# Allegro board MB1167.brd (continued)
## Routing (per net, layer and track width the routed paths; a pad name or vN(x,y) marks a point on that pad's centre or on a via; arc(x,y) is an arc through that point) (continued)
NETR47_1: length 2.4
  TOP w0.127: U6.44 127.27,128.51 R47.1
NETR47_2: length 127.9
  TOP w0.127: v1(125.09,158.62) 125.09,158.37 125.83,157.63 125.83,144.12 125.35,143.64 125.35,137.06 125.83,136.58 125.83,131.47 R47.2
  L4_SIG w0.102: v1(102.36,157.61) 102.87,157.61 103.89,158.62 v1(125.09,158.62)
  BOTTOM w0.127: SB55.2 50.7,131.09 50.7,137.78 55.51,142.59 55.51,147.84 61.49,153.83 64.8,153.83 68.2,157.23 69.47,157.23 69.98,157.73 80.34,157.73 80.92,158.32 93.42,158.32 93.83,158.72 101.24,158.72 v1(102.36,157.61)
NETR48_1: length 2.7
  TOP w0.127: U6.43 127.76,126.15 127.76,127.13 128.52,127.89 R48.1
NETR48_2: length 152.3
  TOP w0.127: v1(126.85,152.91) 126.36,152.43 126.36,132.21 R48.2
  BOTTOM w0.127: v1(126.85,152.91) 126.85,153.92 116.84,163.93 116.84,167.26 114.3,169.8 44.83,169.8 42.04,167 42.04,161.57 36.83,156.37 36.83,141.22 39.5,138.56 40.64,138.56
NETR49_1: length 2.6
  TOP w0.127: U6.39 129.77,127.1 130.18,127.51 R49.1
NETR49_2: length 113.6
  TOP w0.127: v1(128.14,132.97) 128.14,132.84 130.18,130.81 R49.2
  BOTTOM w0.127: SB37.1 48.26,143 51.49,146.23 51.49,149.53 60.71,158.75 62.99,158.75 66.29,162.05 82.55,162.05 83.82,160.78 91.59,160.78 92.46,161.65 111.02,161.65 118.67,154 118.67,152.48 127.51,143.64 127.51,133.6 v1(128.14,132.97)
NETR50_1: length 2.9
  TOP w0.127: U6.38 130.27,127.09 131.44,128.27 R50.1
NETR50_2: length 112.3
  TOP w0.127: R50.2 131.44,130.81 v1(128.14,134.11)
  BOTTOM w0.127: SB29.1 48.9,150.5 48.9,152.78 58.29,162.18 61.34,162.18 61.85,162.69 64.01,162.69 65.15,163.83 109.86,163.83 119.63,154.05 119.63,152.65 128.14,144.15 v1(128.14,134.11)
NETR51_1: length 16.8
  TOP w0.127: U4.P8 73.23,137.67 70.51,137.67 64.52,131.67 R51.1
NETR52_1: length 15.4
  TOP w0.127: R52.1 65.53,131.59 70.85,136.91 71.79,136.91 71.8,136.92 73.18,136.92 U4.P9
NETR53_1: length 14.8
  TOP w0.127: U4.N9 74.01,136.09 71.11,136.09 66.55,131.53 R53.1
NETR54_1: length 12.6
  TOP w0.127: U4.P10 73.21,135.29 71.38,135.29 67.56,131.47 R54.1
NETR55_1: length 10.9
  TOP w0.127: R55.1 68.58,130.86 71.45,133.73 71.88,133.73 72.64,134.49 73.22,134.49 U4.P11
NETR56_2: length 7
  TOP w0.127: R56.2 70.99,128.12 72.64,129.77 72.64,130.94 73.21,131.5 73.21,132.09 U4.P14
NETR57_2: length 6.7
  TOP w0.127: U4.N14 74.02,132.09 74.02,131.29 73.41,130.68 73.41,129.22 72.39,128.21 R57.2
NETR58_2: length 5.7
  TOP w0.127: U4.M15 75.21,131.6 75.06,131.44 75.06,130.84 74.93,130.71 74.93,130.3 74.17,129.54 74.17,128.91 73.79,128.52 R58.2
NETR59_1: length 5.4
  TOP w0.127: U4.L15 76.01,131.13 75.69,130.81 75.69,129.92 75.18,129.41 R59.1
NETR60_1: length 7.2
  TOP w0.127: U4.K13 v5(76.41,132.89) ; R60.1 v3(76.45,127.38)
  BOTTOM w0.127: v3(76.45,127.38) 75.95,127.89 75.95,131.32 76.41,131.78 v5(76.41,132.89)
NETR61_1: length 6.7
  TOP w0.127: R61.1 79.3,126.95 79.3,127.54 78.74,128.1 78.74,128.48 77.98,129.24 77.98,132.06 U4.H14
NETR62_1: length 2.2
  TOP w0.127: U6.1 121.62,124.54 R62.1
NETR62_2: length 113.8
  TOP w0.127: R62.2 121.54,135.2 v1(120.47,136.27)
  BOTTOM w0.127: SB41.2 47.77,139.32 53.01,144.56 53.01,148.77 60.83,156.59 63.3,156.59 66.34,159.64 67.97,159.64 68,159.66 68.08,159.66 68.49,160.07 76.63,160.07 77.34,160.78 81.08,160.78 81.76,160.1 91.85,160.1 92.61,160.86 105.71,160.86 110.62,155.96 110.62,142.09 112.88,139.83 116.84,139.83 120.4,136.27 v1(120.47,136.27)
NETR63_1: length 18.6
  TOP w0.127: U4.R8 70.69,137.29 65.02,131.62 65.02,123.83 R63.1
NETR64_1: length 17.3
  TOP w0.127: U4.R9 72.48,136.49 72.44,136.53 71,136.53 66.04,131.56 66.04,123.83 R64.1
NETR65_1: length 15.9
  TOP w0.127: R65.1 67.06,123.83 67.06,131.5 71.24,135.69 U4.R10
NETR66_1: length 14.2
  TOP w0.127: R66.1 68.07,123.83 68.07,130.94 71.37,134.24 72.01,134.24 72.66,134.89 U4.R11
NETR67_1: length 12.8
  TOP w0.127: U4.R12 72.07,133.35 71.68,133.35 69.01,130.68 69.01,129.03 69.09,128.96 69.09,123.83 R67.1
NETR68_2: length 9.5
  TOP w0.127: U4.P15 73.61,131.39 73.03,130.81 73.03,129.49 71.5,127.97 71.5,124.59 70.99,124.08 R68.2
NETR69_2: length 9.2
  TOP w0.127: R69.2 72.39,123.83 72.9,124.33 72.9,128.18 73.79,129.07 73.79,130.57 74.41,131.19 U4.N15
NETR70_1: length 10.1
  TOP w0.127: R70.1 73.79,123.95 74.3,124.46 74.3,128.49 74.55,128.75 74.55,129.38 75.31,130.14 75.31,131.06 75.62,131.37 75.62,132.09 U4.L14
NETR71_1: length 9.1
  TOP w0.127: R71.1 75.82,123.95 75.82,129.29 76.82,130.29 76.82,131.67 U4.K15
NETR72_1: length 12.1
  TOP w0.127: U4.L12 v5(75.61,133.69) ; R72.1 v3(76.45,124.08)
  BOTTOM w0.127: v3(76.45,124.08) 76.96,124.59 76.96,125.09 76.07,125.98 76.07,127 75.56,127.51 75.56,131.46 76.04,131.94 76.04,133.26 v5(75.61,133.69)
NETR73_1: length 3
  TOP w0.254: R73.1 135,123.06 132.39,123.06 U6.33
NETR74_2: length 124.8
  TOP w0.127: v1(122.28,120.8) R74.2 121.54,121.54 U6.7 ; v1(56.73,41.4) U22.26
  L4_SIG w0.102: v1(116,90.37) 114.02,88.39 114.02,80.01 77.83,43.81 75.62,43.81 73.84,42.04 57.62,42.04 56.99,41.4 v1(56.73,41.4)
  BOTTOM w0.127: v1(116,90.37) 116.23,90.6 116.23,112.14 123.04,118.95 123.04,120.29 122.53,120.8 v1(122.28,120.8)
NETR77_1: length 4.4
  TOP w0.127: R77.1 134.24,118.24 134.24,118.77 132.97,120.04 U6.27
NETR80_2: length 4.7
  TOP w0.254: R80.2 R84.1 v1(12.95,111.25)
  BOTTOM w0.254: T6.1 12.51,111.69 v1(12.95,111.25)
NETR81_1: length 2.6
  TOP w0.127: U6.20 128.77,116.07 R81.1
NETR82_1: length 2.3
  TOP w0.127: U6.21 129.27,115.21 R82.1
NETR83_2: length 3.4
  TOP w0.127: R83.2 132.08,117.19 131.83,117.44 U6.24
NETR88_1: length 5.1
  TOP w0.127: R88.1 33.27,109.98 32.26,109.98 31.62,109.35 31.62,108.2 31.21,107.8 U8.24
NETR90_1: length 7.2
  TOP w0.102: 76.45,107.95 76.45,105.83 U9.F2
  TOP w0.127: 76.45,107.95 76.45,109.98 R91.1 R90.1
NETR94_2: length 5.8
  TOP w0.508: U7.4 19.87,112.59 20.57,111.89 SB15.2 R94.2 SB14.2
NETR95_1: length 3.9
  TOP w0.127: R95.1 31.73,107.29 U8.23
NETR98_2: length 2.6
  TOP w0.127: R98.2 26.58,108.58 U8.32
NETR100_1: length 3.7
  TOP w0.127: U8.22 32.75,106.8 R100.1
NETR102_1: length 3.4
  TOP w0.127: U8.21 33.52,106.29 R102.1
NETR103_1: length 2
  TOP w0.254: R103.1 24.39,106.29 U8.4
NETR105_2: length 5.5
  TOP w0.254: R108.2 R105.2 v1(12.95,106.68)
  BOTTOM w0.254: T7.1 11.75,105.48 v1(12.95,106.68)
NETR106_1: length 3.3
  TOP w0.127: U8.20 33.78,105.8 R106.1
NETR107_1: length 61.7
  TOP w0.102: v5(63.79,76.73) U14.G5 ; v4(82.68,102.37) U9.A5
  TOP w0.127: v1(86.87,103.38) R107.1
  L4_SIG w0.102: v1(86.87,103.38) 86.48,102.99 83.31,102.99 82.68,102.37 v4(82.68,102.37)
  BOTTOM w0.127: v4(82.68,102.37) 82.34,102.37 80,104.7 80,105.66 80.48,106.14 80.48,107.63 79.15,108.97 73.38,108.97 65.02,100.61 65.02,90.65 64.89,90.53 63.37,90.53 63.25,90.4 63.25,80.37 63.12,80.24 61.87,80.24 61.75,80.11 61.75,77.83 62.47,77.1 63.42,77.1 v5(63.79,76.73)
NETR109_1: length 3.6
  TOP w0.127: R109.1 32.88,105.29 U8.19
NETR110_2: length 10
  TOP w0.127: T1.3 18.29,102.7 18.8,103.21 18.8,103.63 R110.2 21.46,104.01 22.35,103.12 25.03,103.12 25.53,103.62 U8.9
NETR115_1: length 4.2
  TOP w0.127: U8.18 31.34,104.8 31.58,105.03 31.88,105.03 R115.1
NETR119_1: length 4.6
  TOP w0.127: U8.17 31.21,104.29 32.89,102.62 32.89,102.11 33.53,101.47 R119.1
NETR121_1: length 99.3
  TOP w0.127: R121.1 22.86,98.55 25.3,96.11 v1(26.57,96.11) ; v1(55.5,33.34) 55.49,33.34 55.23,33.59 U22.29
  L4_SIG w0.102: v1(55.5,33.34) 52.45,33.34 52.13,33.02 51.05,33.02 48.46,30.43 41.68,30.43 37.85,34.26 34.7,34.26 32.05,36.91 32.05,61.93 28.8,65.18 28.8,93.5 26.57,95.73 v1(26.57,96.11)
NETR123_1: length 3.8
  TOP w0.127: R123.1 26.42,101.85 27.05,101.85 27.7,102.5 U8.11
NETR124_1: length 3
  TOP w0.127: R124.1 28.2,102.11 U8.12
NETR125_1: length 2.5
  TOP w0.127: R125.1 28.7,101.1 U8.13
NETR126_1: length 2.9
  TOP w0.127: U8.14 29.2,101.99 29.97,101.22 R126.1
NETR127_1: length 5.5
  TOP w0.127: R127.1 19.94,97.92 18.29,97.92 R128.2 17.34,98.87 T1.1
NETR129_2: length 6.2
  TOP w0.508: R129.2 12.29,97.28 ; R129.2 11.68,96.68 ; R129.2 11.07,97.28 ; 12.6,97.28 R130.1 ; R130.1 13.82,97.28 ; R130.1 13.21,96.68 ; U11.4 11.62,96.46 ; U11.4 12.14,95.69 ; U11.4 11.1,95.69 ; U11.4 11.62,94.91
NETR130_2: length 106.7
  TOP w0.127: U22.17 57.42,32.9 v1(56.9,32.38) ; R130.2 v1(14.99,98.81)
  L4_SIG w0.102: v1(14.99,98.81) 22.73,98.81 28.52,93.01 28.52,65.06 31.72,61.86 31.72,36.84 34.53,34.04 37.69,34.04 41.63,30.1 52.3,30.1 55.11,32.9 56.38,32.9 v1(56.9,32.38)
NETR132_1: length 100.6
  TOP w0.127: v1(57.52,32.23) 57.53,32.23 57.71,32.41 U22.16 ; R132.1 14.15,91.44 18.29,87.3 v1(28.09,87.3)
  L4_SIG w0.102: v1(28.09,87.3) 28.22,87.17 28.22,64.95 31.39,61.77 31.39,36.81 34.45,33.76 37.57,33.76 41.5,29.82 52.63,29.82 55.32,32.51 56.01,32.51 56.64,31.88 57.17,31.88 v1(57.52,32.23)
NETR138_2: length 6.7
  TOP w0.127: R138.2 R139.2 11.43,81.66 10.67,82.42 10.67,83.84 T2.1
NETR146_1: length 7.8
  TOP w0.102: 68.71,73.66 68.71,75.69 68.29,76.11 68.29,76.73 U14.B5
  TOP w0.127: R147.1 R146.1 68.71,71.37 68.71,73.66
NETR150_2: length 1.6
  TOP w0.254: R150.2 38.89,59.05 R151.1
NETR151_2: length 4.3
  TOP w0.254: R152.2 39.4,58.04 37.49,58.04 U17.5
NETR152_1: length 1.3
  TOP w0.254: R153.2 R152.1
NETR154_1: length 131.9
  TOP w0.127: v1(133.4,54.76) 138.15,54.76 138.94,53.98 R155.1 139.83,53.85 141.86,55.88 R154.1 ; v1(55.78,36.83) 55.73,36.88 U22.28
  BOTTOM w0.127: v1(55.78,36.83) 56.29,36.32 56.29,35.66 59.31,32.64 59.31,30.99 63.75,26.54 63.75,24.13 67.44,20.45 125.27,20.45 133.4,28.57 v1(133.4,54.76)
NETR167_1: length 1.9
  TOP w0.127: U22.21 60.22,34.9 R167.1
NETR167_2: length 2
  TOP w0.127: U22.22 59.92,35.41 R167.2
NETR171_2: length 2.2
  TOP w0.127: T3.2 18.1,32.96 17.65,32.51 R171.2
NETR172_1: length 2.2
  TOP w0.127: R172.1 49.16,32.9 U22.44
NETR173_2: length 2.6
  TOP w0.127: U21.44 30.35,32.9 29.21,31.76 R173.2
NETR175_1: length 4.1
  TOP w0.127: R176.1 48.26,29.84 R175.1 48.9,31.62 48.9,32.13 49.17,32.41 U22.45
NETR180_1: length 5.1
  TOP w0.127: U22.2 52.23,28.61 R181.2 49.78,27.05 R180.1
NETR184_2: length 3.5
  TOP w0.127: U21.2 33.44,28.61 33.02,28.19 32.27,28.19 31.25,27.18 R184.2
NETR185_2: length 2.7
  TOP w0.127: U21.3 33.94,28.6 R185.2
NETR188_1: length 12.1
  TOP w0.089: U23.D4 117.86,28.58 118.11,28.83 v2(118.11,28.83) U23.D5
  TOP w0.127: v1(124.26,25.02) 124.26,25.22 R188.1
  L4_SIG w0.102: v2(118.11,28.83) 118.11,28.33 118.72,27.72 118.72,25.4 120.09,24.03 121.97,24.03 122.96,25.02 v1(124.26,25.02)
NETR189_2: length 13.2
  TOP w0.089: U23.F3 v2(119.11,28.33)
  TOP w0.127: v1(126.52,24.92) 126.52,25.68 R189.2
  L4_SIG w0.089: v2(119.11,28.33) 119.11,26.67
  L4_SIG w0.102: v1(126.52,24.92) 125.32,26.11 123.27,26.11 121.56,24.41 120.47,24.41 119.11,25.77 119.11,26.67
NETR193_1: length 4.6
  TOP w0.089: U23.E3 118.61,27.83 118.61,26.69 118.63,26.67
  TOP w0.127: 118.63,26.67 118.63,26.28 119.63,25.27 R193.1
NETR194_2: length 4.9
  TOP w0.089: 119.89,26.67 119.61,26.94 119.61,27.33 U23.G2
  TOP w0.127: R194.2 119.89,26.54 119.89,26.67
NETR195_2: length 5.6
  TOP w0.127: U23.H1 120.76,26.19 121.64,26.19 122.56,25.27 123.24,25.27 123.83,24.69 R195.2
NETR199_1: length 3.4
  TOP w0.127: U24.2 123.78,15.66 123.19,16.26 122.68,16.26 122.43,16 122.43,15.49 R199.1
NETR204_1: length 64.2
  TOP w0.127: v1(57.66,30.73) 57.83,30.9 U22.13 ; R204.1 v1(21.21,15.49)
  BOTTOM w0.127: v1(21.21,15.49) 22.61,14.1 26.29,14.1 30.1,10.29 58.42,10.29 60.71,12.57 60.71,21.72 58.93,23.5 58.93,29.46 v1(57.66,30.73)
NETR205_1: length 58.5
  TOP w0.127: R205.1 v1(23.24,15.49) ; U22.12 57.23,28.68 v1(57.66,28.25)
  BOTTOM w0.127: v1(57.66,28.25) 57.66,28.19 58.55,27.3 58.55,23.11 60.2,21.46 60.2,12.7 58.17,10.67 30.48,10.67 26.29,14.86 23.88,14.86 v1(23.24,15.49)
NETR206_1: length 55.3
  TOP w0.127: R206.1 v1(25.27,15.49) ; U22.11 56.73,28.48 v1(57.66,27.56)
  BOTTOM w0.127: v1(25.27,15.49) 26.42,15.49 30.86,11.05 57.53,11.05 59.56,13.08 59.56,21.46 58.17,22.86 58.17,27.05 v1(57.66,27.56)
NETR207_1: length 52
  TOP w0.127: v1(56.35,28.25) 56.23,28.36 U22.10 ; R207.1 v1(27.3,15.49)
  BOTTOM w0.127: v1(27.3,15.49) 31.11,11.68 57.28,11.68 59.05,13.46 59.05,21.34 57.78,22.61 57.78,26.67 56.35,28.11 v1(56.35,28.25)
NETR225_2: length 19.5
  TOP w0.102: v5(77.22,140.87) 77.99,140.87 U4.H3
  BOTTOM w0.127: R225.2 67.94,152.27 74.17,146.05 74.17,145.67 75.06,144.78 75.07,144.78 75.44,144.41 75.44,143 75.18,142.75 75.18,141.59 75.46,141.32 75.75,141.32 76.04,141.03 76.04,140.73 76.29,140.49 76.94,140.49 77.22,140.77 v5(77.22,140.87)
NETR227_1: length 3.7
  TOP w0.127: U3.8 v1(32.89,152.78)
  BOTTOM w0.127: R227.1 v1(32.89,152.78)
NETR228_2: length 4.2
  TOP w0.127: v1(28.96,152.78) U3.9
  BOTTOM w0.127: R228.2 v1(28.96,152.78)
NETR232_1: length 18.3
  TOP w0.127: v5(76.41,141.69) U4.K3
  BOTTOM w0.127: R232.1 89.03,147.7 85.09,147.7 83.57,146.18 78.33,146.18 77.09,144.94 77.09,143.26 76.81,142.98 76.81,142.09 v5(76.41,141.69)
NETR233_1: length 15.9
  TOP w0.127: v5(77.21,142.49) U4.J2
  BOTTOM w0.127: R233.1 89.66,147.32 85.34,147.32 83.82,145.8 80.84,145.8 80.14,145.1 80.14,144.23 79.46,143.56 77.93,143.56 77.21,142.84 v5(77.21,142.49)
NETR236_1: length 15.7
  TOP w0.127: U4.H2 78.36,142.09 v5(77.99,142.46)
  BOTTOM w0.127: R236.1 89.28,145.92 88.27,146.94 85.6,146.94 84.02,145.36 80.94,145.36 80.52,144.94 80.52,144.08 79.65,143.21 78.05,143.21 77.85,143 77.85,142.6 v5(77.99,142.46)
NETR237_1: length 4.1
  TOP w0.127: U3.1 33.78,143.89 v1(32.64,145.03)
  BOTTOM w0.127: v1(32.64,145.03) R237.1
NETR238_2: length 4.2
  TOP w0.127: U3.15 28.7,145.16 v1(28.83,145.03)
  BOTTOM w0.127: R238.2 v1(28.83,145.03)
NETR239_1: length 12.9
  TOP w0.127: v5(79.61,142.49) U4.G2
  BOTTOM w0.127: v5(79.61,142.49) 79.61,142.5 80.9,143.79 80.9,144.78 81.09,144.97 83.8,144.97 84.14,144.64 84.14,144.59 84.5,144.23 89.37,144.23 R239.1
NETR240_1: length 9.9
  TOP w0.127: v5(81.21,142.49) U4.E2
  BOTTOM w0.127: R240.1 88.52,143.38 88.09,143.81 84.14,143.81 83.64,143.31 82.6,143.31 82.19,142.9 81.86,142.9 81.45,142.49 v5(81.21,142.49)
NETR241_2: length 145.2
  TOP w0.127: U6.5 121.04,122.54 120.62,122.96 120.62,123.42 119.91,124.13 119.91,137.82 122.68,140.59 v1(122.68,155.19)
  BOTTOM w0.127: R241.2 39.24,142.88 37.97,144.15 37.97,155.32 44.7,162.05 51.44,162.05 55.88,166.5 111.25,166.5 122.56,155.19 v1(122.68,155.19)
NETR242_1: length 9.2
  TOP w0.127: v5(82.01,142.49) U4.D2
  BOTTOM w0.127: R242.1 88.01,142.24 86.82,143.43 84.12,143.43 83.72,143.03 82.78,143.03 82.24,142.49 v5(82.01,142.49)
NETR243_2: length 22.7
  TOP w0.127: v1(122.35,123.37) 122.53,123.54 U6.3
  BOTTOM w0.127: v1(122.35,123.37) 122.35,127.25 121.51,128.09 121.51,137.44 117.6,141.35 R243.2
NETR244_2: length 28.3
  TOP w0.127: v1(121.08,123.27) 121.46,122.89 122.52,122.89 122.68,123.04 U6.4
  BOTTOM w0.127: v1(121.08,123.27) 121.34,123.52 121.34,127.13 120.52,127.94 120.52,134.87 116.48,138.91 111.77,138.91 111.23,139.45 109.84,139.45 109.22,140.07 R244.2
NETR245_2: length 9.1
  TOP w0.127: v5(82.01,140.89) U4.D4
  BOTTOM w0.127: R245.2 89.4,139.97 84.44,139.97 83.13,141.27 82.4,141.27 v5(82.01,140.89)
NETR246_2: length 10.2
  TOP w0.127: v5(81.21,140.89) U4.E4
  BOTTOM w0.127: R246.2 89.33,138.3 88.05,139.59 83.93,139.59 83.06,140.46 81.63,140.46 v5(81.21,140.89)
NETR247_1: length 28.3
  TOP w0.127: U6.6 122.76,122.04 122.66,122.15 120.83,122.15 120.14,122.83 v1(120.14,123.19)
  BOTTOM w0.127: R247.1 109.92,136.59 118.17,136.59 120.14,134.62 120.14,127.78 120.9,127.02 120.9,124.64 120.14,123.88 v1(120.14,123.19)
NETR248_2: length 10.8
  TOP w0.102: U4.D5 v5(82.01,140.09)
  TOP w0.127: v1(88.61,137.92) 88.99,138.3 89.53,138.3
  BOTTOM w0.127: v5(82.01,140.09) 82.4,139.7 82.93,139.7 83.43,139.2 87.32,139.2 88.6,137.92 v1(88.61,137.92) 88.61,137.58 89.03,137.16 R248.2
NETR249_2: length 11.8
  TOP w0.127: v5(75.61,140.09) U4.L5
  BOTTOM w0.127: R249.2 67.31,137.79 70.26,140.74 73.3,140.74 73.86,141.3 74.96,141.3 75.23,141.02 75.23,140.72 75.61,140.34 v5(75.61,140.09)
NETR250_2: length 10.2
  TOP w0.127: v5(82.01,139.29) U4.D6
  BOTTOM w0.127: R250.2 89.06,136.02 87.77,137.3 87.77,138.21 87.16,138.82 83.17,138.82 83.08,138.91 82.38,138.91 v5(82.01,139.29)
NETR251_2: length 17.3
  TOP w0.127: U4.J4 77.61,140.45 v5(77.24,140.08)
  BOTTOM w0.127: SB47.1 65.02,135.89 66.67,135.89 R251.2 69.47,137.67 69.47,139.32 70.64,140.49 74.96,140.49 75.18,140.26 75.18,139.95 75.44,139.7 76.56,139.7 76.94,140.08 v5(77.24,140.08)
NETR252_2: length 24.2
  TOP w0.127: U6.2 122.3,124.04 122.08,123.83 120.95,123.83 120.41,124.37 v1(120.41,125.3)
  BOTTOM w0.127: v1(120.41,125.3) 120.41,126.91 119.76,127.56 119.76,134.24 117.91,136.09 113.11,136.09 112.14,135.13 111.84,135.13 111.56,134.85 111.1,134.85 R252.2
NETR253_1: length 11.4
  TOP w0.127: v5(74.01,139.29) U4.N6
  BOTTOM w0.127: R253.1 67.79,134.11 69.09,135.41 69.09,136.17 70.36,137.44 70.36,138.81 70.36,139.12 71.09,139.85 73.2,139.85 73.77,139.29 v5(74.01,139.29)
NETR254_2: length 21
  TOP w0.127: v5(77.21,141.69) U4.J3
  BOTTOM w0.127: R254.2 65.15,134.11 65.79,134.75 67.82,134.75 68.69,135.62 68.69,136.39 69.86,137.55 69.86,139.17 70.93,140.23 73.28,140.23 73.81,139.7 74.98,139.7 75.21,139.47 75.21,139.14 75.46,138.89 76.63,138.89 76.83,139.09 76.83,139.52 77.03,139.71 77.43,139.71 77.62,139.9 77.62,141.27 v5(77.21,141.69)
NETR255_1: length 11.9
  TOP w0.127: v5(74.81,139.29) U4.M6
  BOTTOM w0.127: v5(74.81,139.29) 74.38,138.86 73.86,138.86 73.28,138.28 73.28,137.32 72.99,137.03 71.06,137.03 69.98,135.95 69.98,135.13 67.69,132.84 R255.1
NETR256_1: length 13.5
  TOP w0.127: v5(73.21,139.29) U4.P6
  BOTTOM w0.102: 71.63,139.47 73.03,139.47 v5(73.21,139.29)
  BOTTOM w0.127: R256.1 65.28,132.84 65.79,133.35 67.56,133.35 69.47,135.25 69.47,136.02 70.74,137.29 70.74,138.96 71.25,139.47 71.63,139.47
NETR257_1: length 12.3
  TOP w0.127: v5(74.81,138.49) U4.M7
  BOTTOM w0.127: v5(74.81,138.49) 74.44,138.11 73.95,138.11 73.79,137.95 73.79,137.19 72.87,136.27 71.37,136.27 70.74,135.64 70.74,134.37 67.82,131.44 R257.1
NETR258_1: length 14
  TOP w0.127: v5(74.01,138.49) U4.N7
  BOTTOM w0.127: v5(74.01,138.49) 73.97,138.49 73.53,138.05 73.53,137.25 72.93,136.65 71.22,136.65 70.36,135.79 70.36,134.87 67.69,132.21 66.04,132.21 65.28,131.44 R258.1
NETR262_1: length 7.8
  TOP w0.127: v5(74.81,133.69) U4.M12
  BOTTOM w0.127: v5(74.81,133.69) 74.85,133.69 75.18,133.35 75.18,130.73 75.19,130.72 75.19,130.72 75.18,130.71 R262.1
NETR263_1: length 8.9
  TOP w0.127: v5(74.81,134.49) U4.M11
  BOTTOM w0.127: v5(74.81,134.49) 74.42,134.1 74.42,132.72 74.02,132.31 74.02,128.75 73.79,128.52 R263.1
NETR264_1: length 9.2
  TOP w0.127: v5(74.01,134.49) U4.N11
  BOTTOM w0.127: v5(74.01,134.49) 73.64,134.12 73.64,133.6 73.36,133.32 73.12,133.32 72.84,133.04 72.84,128.85 72.39,128.4 R264.1
NETR265_2: length 10.8
  TOP w0.127: v5(74.01,135.29) U4.N10
  BOTTOM w0.127: R265.2 70.99,128.27 71.88,129.16 71.88,130.43 71.63,130.68 71.63,133.1 73.82,135.29 v5(74.01,135.29)
NETR266_1: length 14.1
  TOP w0.102: v5(75.61,136.89) 75.21,137.29 U4.M8
  BOTTOM w0.127: R266.1 68.58,130.43 74.67,136.52 75.24,136.52 v5(75.61,136.89)
NETR267_1: length 9.1
  TOP w0.127: v5(83.61,133.69) U4.B12
  BOTTOM w0.127: R267.1 86.23,127.15 84.98,128.41 84.98,130.92 84.05,131.85 84.05,133.24 v5(83.61,133.69)
NETR268_2: length 7.3
  TOP w0.127: v5(82.81,132.09) U4.C14
  BOTTOM w0.127: v5(82.81,132.09) 82.81,129.15 84.84,127.13 R268.2
NETR269_2: length 7
  TOP w0.127: v5(82.01,132.09) U4.D14
  BOTTOM w0.127: R269.2 83.44,126.62 82.01,128.05 v5(82.01,132.09)
NETR270_2: length 6.9
  TOP w0.127: v5(81.21,132.09) U4.E14
  BOTTOM w0.127: R270.2 82.04,126.75 81.03,127.76 81.03,131.9 v5(81.21,132.09)
NETR271_2: length 8.6
  TOP w0.127: v5(81.21,133.69) U4.E12
  BOTTOM w0.127: v5(81.21,133.69) 80.8,133.27 80.8,132.74 80.26,132.21 80.26,126.62 R271.2
NETR272_1: length 10.6
  TOP w0.127: v5(74.81,132.89) U4.M13
  BOTTOM w0.127: R272.1 73.79,123.61 74.3,124.11 74.3,127.13 74.8,127.64 74.8,130.56 74.82,130.57 74.82,132.88 v5(74.81,132.89)
NETR273_1: length 11.6
  TOP w0.127: v5(74.01,133.69) U4.N12
  BOTTOM w0.127: v5(74.01,133.69) 74.01,133.57 73.58,133.14 73.58,128.95 72.9,128.27 72.9,124.43 72.39,123.92 R273.1
NETR274_1: length 14.7
  TOP w0.127: v5(74.81,135.29) U4.M10
  BOTTOM w0.127: R274.1 70.99,124.14 71.5,124.65 71.5,128.14 72.26,128.91 72.26,130.81 71.88,131.19 71.88,132.88 73.88,134.87 74.4,134.87 v5(74.81,135.29)
NETR276_1: length 12.7
  TOP w0.127: v5(82.81,133.69) U4.C12
  BOTTOM w0.127: R276.1 85.39,123.37 85.39,127.38 84.6,128.18 84.6,130.42 83.19,131.83 83.19,133.31 v5(82.81,133.69)
NETR277_2: length 11.6
  TOP w0.127: v5(82.81,132.89) U4.C13
  BOTTOM w0.127: v5(82.81,132.89) 82.42,132.5 82.42,128.91 83.95,127.38 83.95,123.19 R277.2
NETR278_2: length 11.6
  TOP w0.127: v5(82.01,132.89) U4.D13
  BOTTOM w0.127: v5(82.01,132.89) 81.64,132.51 81.64,131.67 81.41,131.44 81.41,128.02 82.55,126.87 82.55,123.32 R278.2
NETR279_2: length 11.3
  TOP w0.127: v5(81.21,132.89) U4.E13
  BOTTOM w0.127: v5(81.21,132.89) 81.21,132.77 80.64,132.21 80.64,127.51 81.15,127 81.15,123.7 80.64,123.19 R279.2
NETR285_1: length 3.7
  TOP w0.102: v5(76.71,97.79) 76.5,97.99 76.5,99.97 U9.F7
  BOTTOM w0.102: R285.1 v5(76.71,97.79)
NETR287_1: length 3.2
  TOP w0.102: v5(89.86,81.53) U13.J2
  BOTTOM w0.102: v5(89.86,81.53) 90.32,81.99 90.32,82.7 90.41,82.79
  BOTTOM w0.127: R287.1 91.06,83.44 90.41,82.79
NETR290_2: length 2.4
  TOP w0.127: v1(51.31,34.29) 50.92,33.9 U22.42
  BOTTOM w0.127: v1(51.31,34.29) 51.82,34.29 R290.2
NETR291_2: length 2.2
  TOP w0.127: v1(51.31,33.53) 51.18,33.53 51.06,33.41 U22.43
  BOTTOM w0.127: R291.2 52.07,33.53 v1(51.31,33.53)
NETR292_2: length 2.7
  TOP w0.127: U21.20 40.91,34.41 v1(41.15,34.16)
  BOTTOM w0.127: v1(41.15,34.16) 40.39,33.4 R292.2
NETR293_1: length 4.3
  TOP w0.127: v1(20.7,32.51) 20.59,32.51 T3.1
  BOTTOM w0.127: R293.1 R296.2 20.57,32.51 v1(20.7,32.51) R294.1
NETR295_2: length 2.2
  TOP w0.127: v1(51.31,32.13) 51.08,31.9 U22.46
  BOTTOM w0.127: R295.2 v1(51.31,32.13)
NETSB9_2: length 57.9
  TOP w0.127: v1(126.87,143.13) 126.87,132.31 128.37,130.81 128.91,130.81 129.16,130.56 129.16,127.69 128.77,127.29 U6.41 ; 91.31,138.3 92.27,138.3 93.54,137.03 107.57,137.03 108.08,137.54 v1(108.08,137.67)
  L4_SIG w0.102: v1(108.08,137.67) 108.2,137.54 112.01,137.54 112.27,137.79 112.27,138.89 113.46,140.08 116.46,140.08 117.96,141.58 125.45,141.58 126.87,143 v1(126.87,143.13)
NETSB14_1: length 117.9
  TOP w0.127: v1(55.5,32) 54.73,32.77 U22.30 ; v1(16.13,98.17) 16.51,98.55 16.51,106.81 17.65,107.95 SB14.1
  L4_SIG w0.102: v1(16.13,98.17) 16.43,98.48 22.55,98.48 27.66,93.37 27.66,87.12 27.94,86.84 27.94,64.81 31.11,61.63 31.11,36.67 34.35,33.43 37.44,33.43 41.4,29.46 52.96,29.46 v1(55.5,32)
NETSB15_1: length 6.3
  TOP w0.127: U8.3 25.03,106.8 24.38,107.44 21.97,107.44 SB15.1
NETSB18_1: length 87.2
  TOP w0.089: U23.D3 117.61,27.84 117.61,26.67
  TOP w0.127: v1(126.57,94.08) 127.46,94.97 127.46,97.71 129.54,99.8 SB18.1 ; 117.61,26.67 117.61,25.01 v1(117.6,24.99)
  L4_SIG w0.089: 116.48,31.5 117.09,30.89 117.09,29.34 117.73,28.7 117.73,26.67
  L4_SIG w0.102: 117.73,26.67 117.73,25.12 v1(117.6,24.99) ; 116.48,31.5 113.41,34.57 113.41,46.81 116,49.4 116,75.74 118.26,78 118.26,86 122.49,90.23 123.1,90.23 126.57,93.7 v1(126.57,94.08)
NETSB20_2: length 139.7
  TOP w0.127: U25.3 3.77,7.83 v1(2.92,6.99) ; v1(121.16,13.97) 121.54,13.59 122.94,13.59 123.19,13.84 123.19,14.22 123.78,14.82 U24.3
  BOTTOM w0.127: v1(2.92,6.99) 4.83,8.89 15.14,8.89 17.17,10.92 25.02,10.92 34.04,1.91 49.01,1.91 52.64,5.53 61.79,5.53 68.83,12.57 78.37,12.57 82.43,8.51 103.25,8.51 109.54,14.8 117.09,14.8 117.92,13.97 119.89,13.97 SB20.2 v1(121.16,13.97)
NETSB21_1: length 143.6
  TOP w0.127: v1(6.48,6.99) 5.63,7.83 U25.4 ; U24.4 125.65,14.82 126.36,14.1 126.62,14.1 v1(126.75,13.97)
  BOTTOM w0.127: v1(6.48,6.99) 7.87,8.38 15.62,8.38 17.65,10.41 23.62,10.41 32.77,1.27 49.28,1.27 53.09,5.08 62.1,5.08 68.96,11.94 78.11,11.94 82.3,7.75 103.76,7.75 109.86,13.84 116.84,13.84 117.47,13.21 117.47,12.83 120.27,10.03 124.84,10.03 125.98,11.18 125.98,13.21 v1(126.75,13.97) 127.51,14.73 127.51,15.11 127.64,15.24
NETSB32_1: length 204.1
  TOP w0.089: U23.E4 118.61,28.83 118.96,28.83 118.96,28.83 119.26,28.83 119.26,28.83 119.46,28.83 119.46,28.83 119.76,28.83 119.76,28.83 120.4,28.83
  TOP w0.127: v1(121.84,27.05) 121.84,27.53 120.55,28.83 120.4,28.83
  L4_SIG w0.102: v1(36.7,125.73) 37.03,126.06 37.03,127.43 35.86,128.6 35.86,143.12 38.61,145.86 38.61,146.81 39.12,147.32 v1(39.24,147.32)
  BOTTOM w0.127: v1(121.84,27.05) 121.92,26.97 121.92,24.83 119.6,22.52 96.65,22.52 95.72,21.59 68.07,21.59 65.02,24.64 65.02,48.31 61.9,51.44 61.9,60.66 53.24,69.32 53.24,78.87 43.28,88.82 43.28,108.23 37.47,114.05 37.47,124.97 v1(36.7,125.73) ; v1(39.24,147.32) SB32.1
NETSB36_1: length 139.1
  TOP w0.127: v1(129.49,145.19) 129.49,141.71 127.25,139.47 127.25,132.44 128.4,131.29 129.01,131.29 129.54,130.76 129.54,127.38 129.27,127.11 U6.40
  BOTTOM w0.127: v1(129.49,145.19) 129.49,146.96 121.41,155.04 121.41,155.19 110.49,166.12 57.25,166.12 52.32,161.19 44.73,161.19 38.35,154.81 38.35,145.36 39.44,144.28 40.5,144.28 SB36.1
NETSB47_2: length 107.9
  TOP w0.127: U6.42 128.27,124.58 127.25,123.57 v1(127.25,122.94)
  L4_SIG w0.102: v1(51.31,118.36) 51.82,118.87 56.69,118.87 58.65,116.92 76.3,116.92 76.66,116.56 98.6,116.56 101.32,119.28 108.76,119.28 111.05,116.99 116.92,116.99 122.86,122.94 v1(127.25,122.94)
  BOTTOM w0.127: SB47.2 62.1,135.51 52.68,126.09 52.68,119.74 v1(51.31,118.36)
NETSB49_1: length 107.3
  TOP w0.127: v1(107.49,74.9) 107.49,72.64 127.3,52.83 127.3,42.16
  TOP w0.155: 127.3,42.16 127.3,40.84 128.14,40.01 U20.1
  BOTTOM w0.127: SB49.1 117.88,129.9 117.88,127.48 118.41,126.95 118.41,122.28 118.72,121.97 118.72,119.66 113.49,114.43 113.49,92.58 113.04,92.14 113.04,80.45 v1(107.49,74.9)
NETTP12_1: length 6.7
  TOP w0.127: U6.25 132.93,119.04 133.35,118.62 133.35,115.95 TP12.1
NETU22_15: length 78.7
  TOP w0.089: 120.4,28.33 119.61,28.33 U23.G3
  TOP w0.127: v1(122.61,27.05) 122.07,26.52 121.72,26.52 121.18,27.05 121.18,27.56 120.41,28.33 120.4,28.33 ; U22.15 v1(60.42,31.9)
  BOTTOM w0.127: v1(122.61,27.05) 122.56,27 122.56,24.64 120.02,22.1 97.16,22.1 96.14,21.08 67.82,21.08 64.39,24.51 64.39,26.92 60.42,30.89 v1(60.42,31.9)
OSC_IN: length 11.5
  TOP w0.203: X6.2 34.16,22.23 34.92,22.99 34.92,26.25 34.04,27.14 C80.1 34.04,27.22 34.94,28.12 U21.5
OSC_OUT: length 11.9
  TOP w0.203: 39.81,22.23 X6.1 35.94,22.23 35.43,22.73 35.43,26.25 36.32,27.14 C81.1 36.32,27.22 35.44,28.1 U21.6
PA0: length 41
  TOP w0.127: CN5.15 v1(43.41,147.07) ; v5(74.01,141.69) U4.N3
  L4_SIG w0.102: v5(74.01,141.69) 73.94,141.76 69.19,141.76 67.44,140 65.53,140 63.7,141.83 61.42,141.83 59.74,143.51 52.12,143.51 49.96,145.67 45.75,145.67 45.01,146.41 44.07,146.41 v1(43.41,147.07)
  BOTTOM w0.127: 42.29,147.07 v1(43.41,147.07) ; SB32.2 SB34.2 SB36.2
PA1: length 37.7
  TOP w0.127: CN5.14 v1(44.7,148.34) ; U4.N2 v5(74.01,142.49)
  L4_SIG w0.102: v5(74.01,142.49) 73.57,142.93 73.06,142.93 72.48,143.51 69.6,143.51 68.58,144.53 65.41,144.53 64.06,145.87 53.52,145.87 51.05,148.34 v1(44.7,148.34)
  BOTTOM w0.127: v1(44.7,148.34) 45.59,149.22 SB29.2 SB23.2
PA2: length 38
  TOP w0.127: U4.P2 v5(73.21,142.49) ; CN5.13 v1(43.43,148.34)
  L4_SIG w0.102: v5(73.21,142.49) 73.05,142.65 67.53,142.65 66.16,144.02 62.99,144.02 v1(62.61,144.4) 61.49,145.52 53.11,145.52 50.93,147.7 44.07,147.7 v1(43.43,148.34)
  BOTTOM w0.127: v1(43.43,148.34) 42.93,148.84 SB30.2 SB24.2
PA3: length 108.4
  TOP w0.127: v1(44.83,145.8) CN5.18 49.15,145.8 50.7,144.25 61.37,144.25 62.79,145.67 64.52,145.67 65.02,145.16 65.02,144.15 66.12,143.05 71.45,143.05 72.42,142.09 U4.R2 ; R88.2 34.92,110.11 v1(34.8,110.11)
  L4_SIG w0.102: v1(44.83,145.8) 44.2,145.8 43.69,146.3 40.51,146.3 40.39,146.18 40.39,145.97 40.51,145.85 42.81,145.85 42.93,145.73 42.93,145.56 42.81,145.44 40.51,145.44 40.39,145.32 40.39,145.15 40.51,145.03 42.93,145.03 43.05,144.91 43.05,144.75 42.93,144.63 39.87,144.63 39.75,144.51 39.75,144.34 39.87,144.22 43.06,144.22 43.18,144.1 43.18,143.93 43.06,143.81 39.12,143.81 38.99,143.69 38.99,143.48 39.12,143.36 42.81,143.36 42.93,143.24 42.93,143.07 42.81,142.95 38.1,142.95 37.8,142.65 37.8,138.86 37.08,138.15 37.08,131.37 37.8,130.66 37.8,112.8 37.51,112.52 37.37,112.52 36.83,113.06 36.68,113.06 36.54,112.92 36.54,112.77 37.08,112.23 37.08,112.09 36.94,111.94 36.79,111.94 36.25,112.48 36.11,112.48 35.96,112.34 35.96,112.2 36.5,111.65 36.5,111.51 36.36,111.37 36.22,111.37 35.68,111.91 35.53,111.91 35.39,111.77 35.39,111.62 35.93,111.08 35.93,110.94 35.79,110.79 35.64,110.79 35.1,111.33 34.96,111.33 34.81,111.19 34.81,111.05 35.35,110.5 35.35,110.36 35.1,110.11 v1(34.8,110.11)
PA4: length 162.7
  TOP w0.127: CN5.21 v1(43.41,143.26) ; CN4.31 147.54,141.69 v1(147.35,141.88) ; U4.N4 v5(74.01,140.89)
  L4_SIG w0.102: v1(147.35,141.88) 145.41,143.81 143.89,143.81 141.63,146.08 125.12,146.08 v1(124.71,145.67) ; v5(74.01,140.89) 71.24,140.89 69.48,139.13 64.25,139.13 62.51,140.87 58.19,140.87 56.57,142.49 51.61,142.49 50.22,143.89 44.04,143.89 v1(43.41,143.26)
  BOTTOM w0.127: v1(124.71,145.67) 118.24,152.15 118.24,153.44 112.75,158.93 110.57,158.93 108.16,161.33 92.55,161.33 91.74,160.53 82.93,160.53 81.79,161.67 68.71,161.67 67.69,160.66 65.41,160.66 63.12,158.37 60.83,158.37 51.87,149.4 51.87,145.85 48.18,142.16 45.42,142.16 44.96,142.62 44.04,142.62 v1(43.41,143.26)
PA5: length 108.9
  TOP w0.127: R126.2 v1(30.73,100.33) ; v1(44.83,141.99) CN5.24 49.15,141.99 49.53,141.6 61.85,141.6 62.9,140.55 65.24,140.55 65.71,140.08 67.31,140.08 68.15,140.92 73.18,140.92 73.61,140.49 U4.P4
  L4_SIG w0.102: v1(30.73,100.33) 32.46,100.33 32.59,100.46 32.59,108.97 32.72,109.09 34.54,109.09 38.18,112.73 38.18,135.11 38.07,135.21 37.52,135.21 37.41,135.31 37.41,135.51 37.52,135.62 38.07,135.62 38.18,135.72 38.18,135.92 38.07,136.02 37.52,136.02 37.41,136.12 37.41,136.33 37.52,136.43 38.07,136.43 38.18,136.53 38.18,136.73 38.07,136.83 37.52,136.83 37.41,136.94 37.41,137.14 37.52,137.24 38.07,137.24 38.18,137.34 38.18,137.55 38.07,137.65 37.52,137.65 37.41,137.75 37.41,137.95 37.52,138.05 38.07,138.05 38.18,138.16 38.18,141.55 38.23,141.6 42.67,141.6 42.8,141.73 42.8,142.04 42.68,142.16 38.2,142.16 38.1,142.27 38.1,142.49 38.23,142.62 49.15,142.62 49.28,142.49 49.28,142.11 49.15,141.99 v1(44.83,141.99)
PA6: length 109.3
  TOP w0.102: U4.P3 73.19,141.71 72.16,141.71 71.63,142.24
  TOP w0.127: 71.63,142.24 71.25,142.62 65.41,142.62 64.26,143.76 50.27,143.76 49.5,144.53 CN5.20 v1(44.83,144.53) ; SB5.2 107.19,158.62 R14.2 107.95,159.64 107.95,162.31 v1(107.31,162.94)
  BOTTOM w0.127: v1(107.31,162.94) 105.97,162.94 105.69,162.66 86.87,162.66 86.36,162.15 85.39,162.15 84.73,162.81 66.14,162.81 62.97,159.64 60.45,159.64 50.72,149.91 50.72,147.37 48.64,145.29 45.15,145.29 44.83,144.97 v1(44.83,144.53)
PA7: length 32
  TOP w0.127: U4.R3 71.88,141.29 70.98,142.19 65.91,142.19 65.2,141.48 62.61,141.48 60.83,143.26 CN5.22 v1(44.83,143.26)
  BOTTOM w0.127: 46.18,144.45 46.18,143.18 44.91,143.18 v1(44.83,143.26)
PA8: length 49.2
  TOP w0.127: CN6.52 114.02,124.21 v1(113.49,124.74) ; U4.F15 80.01,129.16 83.24,125.93 86.66,125.93 v1(86.89,125.7)
  L4_SIG w0.102: v1(86.89,125.7) 87.3,125.3 88.01,125.3 89.18,126.47 103.68,126.47 106.88,129.67 110.49,129.67 113.03,127.13 113.03,125.2 v1(113.49,124.74)
  BOTTOM w0.127: SB56.2 SB57.2 SB60.2 114.27,123.95 v1(113.49,124.74)
PA9: length 41.4
  TOP w0.127: U4.E15 80.81,129.38 82.93,127.25 v1(83.44,127.25) ; CN6.43 v1(112.01,129.29)
  L4_SIG w0.102: v1(83.44,127.25) 85.07,127.25 85.93,126.39 88.16,126.39 88.8,127.03 103.05,127.03 106.32,130.3 110.74,130.3 111.76,129.29 v1(112.01,129.29)
  BOTTOM w0.127: v1(112.01,129.29) SB54.2 R261.1
PA10: length 302
  TOP w0.127: R117.2 8.89,103.5 v1(9.02,103.63) ; v1(19.94,119.25) 20.07,119.38 22.35,119.38 24.26,121.28 36.83,121.28 41.05,117.07 v1(45.69,117.07) ; v5(82.91,127.86) 82.91,127.91 81.61,129.21 U4.D15 ; JP14.2 57.15,19.81 74.3,19.81 76.71,22.23 v1(76.71,25.27) ; v1(113.28,129.29) CN6.44
  L4_SIG w0.102: v5(82.91,127.86) 85.19,127.86 86.39,126.67 88.01,126.67 88.67,127.33 102.87,127.33 106.2,130.66 110.87,130.66 111.73,129.79 112.17,129.79 112.67,129.29 v1(113.28,129.29) 113.39,129.29 114.07,128.6 114.07,123.32 112.98,122.22 112.6,122.22 112.12,122.71 110.46,122.71 108.66,120.9 98.3,120.9 96.14,118.75 59.82,118.75 57.91,120.65 49.73,120.65 46.41,117.32 45.95,117.32 v1(45.69,117.07)
  BOTTOM w0.127: v1(76.71,25.27) 75.18,26.8 75.18,29.46 74.36,30.29 74.36,49.39 68,55.75 68,64.21 58.8,73.41 58.8,83.82 49.66,92.96 49.66,111.63 45.69,115.6 v1(45.69,117.07) ; v1(19.94,119.25) 17.27,119.25 14.22,116.2 14.22,110.74 11.68,108.2 10.16,108.2 9.02,107.06 v1(9.02,103.63)
PA11: length 204
  TOP w0.127: v1(86.92,127.1) 86.72,127.3 84.38,127.3 82.41,129.27 U4.C15 ; v1(111.94,130.56) CN6.41
  TOP w0.155: v1(9.23,99.04) 9.09,99.18 8.56,99.18 D5.D3
  L4_SIG w0.102: v1(111.94,130.56) 111.46,131.04 105.74,131.04 102.41,127.71 88.01,127.71 87.6,127.3 87.12,127.3 v1(86.92,127.1)
  L4_SIG w0.13: v1(9.23,99.04) 9.37,99.18 9.97,99.18 10.41,99.62 24.02,99.62 25.62,98.02 33.43,98.02 38.43,103.02 38.43,105.15 48.26,114.98 48.26,117.09 50.63,119.46 57.35,119.46 59.05,117.75 97.06,117.75 99.4,120.09 109.23,120.09 110.47,121.34 113.44,121.34 115.19,123.09 115.19,130.18 114.38,130.99 112.98,130.99 112.5,130.51 111.99,130.51 v1(111.94,130.56)
  BOTTOM w0.127: JP8.1 112.42,106.32 112.42,114.33 118.11,120.02 118.11,121.67 117.83,121.95 117.83,126.77 116.59,128.02 112.8,128.02 112.55,128.27 112.55,129.95 v1(111.94,130.56) ; v1(9.23,99.04) 8.89,98.7 R284.2
  BOTTOM w0.155: 110.74,130.56 v1(111.94,130.56)
PA12: length 43.7
  TOP w0.127: v1(86.87,127.81) 86.69,127.64 84.61,127.64 82.8,129.44 82.8,131.28 U4.B15 ; v1(112.78,131.83) 114.05,130.56 CN6.42
  L4_SIG w0.102: v1(112.78,131.83) 112.27,131.32 105.54,131.32 102.23,128.02 87.86,128.02 87.48,127.64 87.05,127.64 v1(86.87,127.81)
  BOTTOM w0.127: SB48.2 SB49.2 SB52.2 114.43,130.18 v1(112.78,131.83)
PA13: length 272.4
  TOP w0.127: v1(87.5,128.4) 87.63,128.52 87.63,130.35 86.66,131.32 84.38,131.32 U4.A15 ; R86.2 126.49,111.12 v1(127,110.62) ; v1(146.18,139.32) 146.18,135.38 145.54,134.75 145.54,130.05 147.57,128.02 149.61,128.02 150.24,127.38 150.24,126.24 v1(150.75,125.73) ; CN6.40 114.07,131.83 v1(113.49,132.41) ; U21.27 37.44,38.83 v1(37.72,39.12) 38.14,39.12 38.44,38.82 U21.25
  L4_SIG w0.102: v1(37.72,39.12) 37.72,37.74 39.62,35.84 39.62,34.8 40.82,33.6 41.66,33.6 42.62,32.64 48.34,32.64 49.53,33.83 49.53,38.38 51.92,40.77 57.28,40.77 58.17,41.66 74.07,41.66 75.79,43.38 77.9,43.38 114.4,79.88 114.4,88.06 125.96,99.62 125.96,100.43 126.9,101.37 127.76,101.37 129.06,102.67 129.06,104.88 126.49,107.44 126.49,110.11 v1(127,110.62) 132.08,110.62 133.73,112.27 135.27,112.27 139.74,116.74 142.48,116.74 146.16,120.42 149.69,120.42 150.75,121.48 v1(150.75,125.73) ; v1(87.5,128.4) 88.34,129.24 94.59,129.24 98.45,133.1 111.12,133.1 111.46,132.77 113.13,132.77 v1(113.49,132.41) 120.24,132.41 132.84,145.01 140.11,145.01 145.9,139.22 146.08,139.22 v1(146.18,139.32)
PA14: length 269.8
  TOP w0.127: CN6.36 v1(113.16,134.37) ; U4.A14 86.98,132.49 87.28,132.18 v1(87.35,132.18) ; v1(37.59,36.7) 37.94,37.05 U21.26 ; v1(146.94,140.08) 147.07,139.95 147.07,135.38 146.05,134.37 146.05,130.18 147.83,128.4 149.99,128.4 150.75,127.64 v1(150.75,126.75) ; v1(127,109.6) 126.75,109.86 R93.2 ; U21.15 41.63,31.9 42.04,32.31 42.11,32.31 v1(42.13,32.32)
  L4_SIG w0.102: v1(87.35,132.18) 87.39,132.14 94.75,132.14 97.74,135.13 112.01,135.13 112.78,134.37 v1(113.16,134.37) 121.59,134.37 132.54,145.31 140.31,145.31 145.54,140.08 v1(146.94,140.08) ; v1(150.75,126.75) 151.26,126.24 151.26,121.63 149.8,120.17 146.27,120.17 142.58,116.48 139.84,116.48 135.37,112.01 133.99,112.01 132.11,110.13 127.53,110.13 v1(127,109.6) 126.9,109.5 126.9,107.59 129.46,105.03 129.46,102.41 114.81,87.76 114.81,79.68 78.08,42.95 76.12,42.95 72.54,39.37 56.13,39.37 55.12,40.39 52.02,40.39 49.89,38.25 49.89,33.68 48.53,32.32 v1(42.13,32.32) 42.05,32.32 41.86,32.51 41.86,32.84 41.43,33.27 40.64,33.27 38.23,35.69 38.23,36.07 v1(37.59,36.7)
PA15: length 266.8
  TOP w0.127: R101.2 127.13,107.31 128.14,108.33 v1(128.27,108.33) ; v1(112.78,137.16) 113.41,136.53 113.92,136.53 114.3,136.91 CN6.32 ; v1(147.14,140.84) 147.31,140.84 148.08,140.07 148.08,139.57 147.83,139.32 147.83,135.16 147.83,134.62 146.81,133.6 146.81,130.68 148.34,129.16 150.3,129.16 151.64,127.82 151.64,126.81 v1(151.7,126.75) ; U21.17 40.63,32.9 v1(41.1,32.44) ; U4.A13 v5(86.23,133.29)
  L4_SIG w0.102: v1(151.7,126.75) 151.7,126.68 152.27,126.11 152.27,121.59 149.81,119.13 146.3,119.13 142.9,115.72 140.16,115.72 135.69,111.25 134.37,111.25 132.14,109.03 128.59,109.03 128.27,108.71 v1(128.27,108.33) 128.14,108.2 128.14,107.64 130.07,105.71 130.07,102.01 115.44,87.38 115.44,79.27 74.85,38.68 55.8,38.68 54.74,39.75 53.34,39.75 50.77,37.19 50.77,33.25 48.39,30.86 45.97,30.86 45.19,31.65 41.78,31.65 41.1,32.33 v1(41.1,32.44) ; v1(147.14,140.84) 145.19,140.84 140.28,145.75 132.36,145.75 122.12,135.51 114.43,135.51 v1(112.78,137.16) 112.65,137.16 112.27,136.78 109.09,136.78 108.46,136.14 97.23,136.14 94.06,132.97 86.55,132.97 v5(86.23,133.29)
PAR_D0: length 120.4
  TOP w0.127: v1(120.52,147.9) 118.29,145.67 118.29,121.34 117.35,120.4 CN6.58 114.17,120.4 113.59,120.98 113.59,121.93 v1(112.81,122.71) ; JP4.3 107.86,129.03 v1(108.04,128.85) ; CN4.23 147.65,145.69 146.99,145.03 v1(146.94,145.03) ; v1(79.12,128.85) 78.61,129.36 78.61,130.61 78.41,130.81 U4.H15
  L4_SIG w0.102: v1(112.81,122.71) 112.81,122.72 112.39,123.14 112.39,126.87 110.41,128.85 v1(108.04,128.85) 108.03,128.84 107.53,128.84 107.31,128.63 107.31,126.62 106.22,125.53 89.76,125.53 88.19,123.95 87.2,123.95 86,125.15 83.34,125.15 79.63,128.85 v1(79.12,128.85) ; v1(120.52,147.9) 122.56,147.9 123.01,147.45 141.99,147.45 144.17,145.26 146.71,145.26 v1(146.94,145.03)
  BOTTOM w0.127: v1(112.81,122.71) 112.88,122.71 113.16,122.43 SB62.1
PAR_D1: length 174.2
  TOP w0.127: U4.G15 79.27,131.62 79.27,129.64 v1(79.15,129.51) ; v1(95.63,156.84) 95.63,157.86 94.61,158.88 94.61,166.65 CN1.7 ; v1(120.35,149) 117.93,146.58 117.93,123.14 116.46,121.67 CN6.56 114.3,121.67 113.59,122.38 113.59,122.61 v1(112.83,123.37) ; v1(150.5,144.78) 151,144.78 151.64,145.41 152.17,145.41 CN4.24
  L4_SIG w0.102: v1(150.5,144.78) 150.26,144.55 147.8,144.55 147.45,144.91 147.45,145.36 146.93,145.87 144.2,145.87 142.04,148.03 123.27,148.03 122.3,149 v1(120.35,149) ; v1(112.83,123.37) 112.65,123.55 112.65,127.13 110.44,129.34 107.24,129.34 104.04,126.14 89.43,126.14 88.27,124.97 86.87,124.97 86.39,125.45 83.52,125.45 79.45,129.51 v1(79.15,129.51)
  BOTTOM w0.127: R280.1 113.7,120.9 112.37,122.23 112.37,122.91 v1(112.83,123.37) 112.83,123.42 112.88,123.47 112.88,125.55 111.43,127 107.75,127 107.29,127.46 107.29,132.61 105.82,134.09 105.82,151.41 100.81,156.41 100.2,156.41 98.97,157.65 96.43,157.65 v1(95.63,156.84)
PAR_D2: length 140.5
  TOP w0.127: CN4.25 148.42,144.69 v1(148.08,145.03) ; v1(87.44,124.49) 87.27,124.49 86.28,125.48 83.13,125.48 79.61,129 79.61,132.09 U4.G14 ; v1(106.05,126.09) 106.05,125.35 107.19,124.21 CN6.51
  L4_SIG w0.102: v1(106.05,126.09) 105.79,125.83 89.61,125.83 88.27,124.49 v1(87.44,124.49) ; v1(148.08,145.03) 148.59,145.54 148.59,156.08 148.08,156.59 147.45,156.59 146.1,157.94 124.79,157.94 124.49,158.24 107.57,158.24 105.99,156.67 100.03,156.67 v1(98.93,155.57)
  BOTTOM w0.127: v1(98.93,155.57) 99.47,155.57 104.42,150.62 104.42,133.35 105.94,131.83 105.94,126.19 v1(106.05,126.09) 106.05,125.98 108.08,123.95 SB61.1 SB58.1
PAR_D3: length 94.9
  TOP w0.127: CN4.26 152.08,144.69 151.28,143.89 v1(151.28,143.81) ; v1(87.57,125.73) 86.91,126.39 83.29,126.39 80.39,129.29 80.39,132.11 U4.F14 ; CN6.46 114.07,128.02 113.56,128.52 v1(113.28,128.52)
  L4_SIG w0.102: v1(151.28,143.81) 151.64,143.46 151.64,142.49 151.13,141.99 149.86,141.99 148.87,141 148.87,140.21 147.03,138.37 145.81,138.37 139.9,144.27 133.35,144.27 118.36,129.29 v1(117.35,129.29) ; v1(87.57,125.73) 87.96,125.73 88.95,126.72 103.3,126.72 106.55,129.97 110.59,129.97 112.04,128.52 v1(113.28,128.52)
  BOTTOM w0.127: v1(117.35,129.29) 115.6,129.29 115.34,129.03 114.94,129.03 R260.2 114.43,128.52 v1(113.28,128.52)
PAR_D4: length 149.5
  TOP w0.127: U4.B13 83.61,132.89 87.46,132.89 94.36,125.98 94.36,124.33 95.76,122.94 CN6.53 111.56,122.94 v1(111.89,123.27) ; CN4.27 v1(148.08,143.69)
  L4_SIG w0.102: v1(148.08,143.69) 148.15,143.76 150.11,143.76 151,144.65 151,144.91 150.62,145.29 149.93,145.29 148.99,146.23 148.99,156.57 147.24,158.32 126.29,158.32 125.48,159.13 103.76,159.13 102.88,158.25 102.35,158.25 101.07,156.97 98.04,156.97 v1(97.84,157.18)
  BOTTOM w0.127: R275.2 111.56,122.94 v1(111.89,123.27) 112.37,123.75 112.37,125.35 111.1,126.62 107.62,126.62 106.96,127.28 106.96,132.41 105.44,133.93 105.44,151.28 100.63,156.08 99.95,156.08 98.86,157.18 v1(97.84,157.18)
PAR_D5: length 80.1
  TOP w0.127: CN4.28 152,143.69 151.18,142.88 v1(150.5,142.88) ; v1(111.86,143.26) 111.86,142.75 111.1,141.99 CN6.23 ; v5(82.81,134.49) U4.C11
  L4_SIG w0.102: v1(150.5,142.88) 147.07,142.88 145.72,144.22 144.07,144.22 141.81,146.48 124.13,146.48 120.41,142.77 113.27,142.77 112.78,143.26 v1(111.86,143.26) 110.74,143.26 107.95,140.46 98.42,140.46 94.36,136.4 86.06,136.4 84.68,135.03 83.35,135.03 v5(82.81,134.49)
PAR_D6: length 73.2
  TOP w0.127: CN4.29 147.86,142.69 146.15,144.4 v1(146.15,146.51) ; SB4.1 91.19,149.58 93.8,152.2 v1(93.8,155.35)
  L4_SIG w0.102: v1(93.8,155.35) 94.26,154.89 107.52,154.89 109.68,157.05 113.46,157.05 116.26,154.25 128.42,154.25 129.54,153.14 129.54,149.94 131.06,148.41 142.54,148.41 144.45,146.51 v1(146.15,146.51)
PAR_D7: length 60.8
  TOP w0.127: v1(155.19,142.98) 154.56,142.98 154.28,142.69 CN4.30 ; SB16.1 v1(131.9,104.65)
  L4_SIG w0.102: v1(131.9,104.65) 131.9,106.15 133.96,108.2 136.22,108.2 141.33,113.31 143.13,113.31 146.43,116.61 153.82,116.61 155.93,118.72 155.93,142.67 155.63,142.98 v1(155.19,142.98)
PAR_D8: length 249.4
  TOP w0.127: v1(150.5,152.91) 150.28,152.69 CN4.9 ; v1(111.86,122.17) 111.58,122.17 111.07,121.67 CN6.55 95.63,121.67 93.47,123.83 93.47,126.28 88.06,131.7 86.81,131.7 86.45,132.06 83.64,132.06 U4.B14 ; R16.2 28.07,157.35 v1(29.72,157.35)
  L4_SIG w0.102: v1(29.72,157.35) 32.89,157.35 35.69,160.15 42.55,160.15 43.43,161.04 66.04,161.04 66.8,161.8 81.66,161.8 83.19,160.27 94.11,160.27 96.16,158.22 97.56,158.22 98.55,157.23 100.84,157.23 102.36,158.75 102.74,158.75 103.63,159.64 106.68,159.64 108.58,161.54 119.89,161.54 121.67,159.77 126.11,159.77 126.87,159 147.57,159 149.73,156.84 149.73,153.8 150.5,153.03 v1(150.5,152.91) 151,152.91 151.51,152.4 151.51,150.62 151.13,150.24 150.37,150.24 150.11,149.99 150.11,146.81 150.5,146.43 151.38,146.43 152.65,145.16 152.65,141.68 152.04,141.07 150.52,141.07 150.22,140.77 150.22,140.03 147.66,137.48 145.71,137.48 139.47,143.71 133.78,143.71 116.23,126.16 116.23,122.48 113.89,120.14 v1(113.89,118.24)
  BOTTOM w0.127: R281.2 111.23,121.39 111.23,121.54 v1(111.86,122.17) 111.99,122.17 113.89,120.27 v1(113.89,118.24)
PAR_D9: length 236.1
  TOP w0.127: v1(107.44,156.88) 109,156.88 111.51,159.38 111.51,162.94 v1(111.63,163.07) ; CN16.5 v1(140.52,48.57) ; v5(86.76,133.35) 86.74,133.35 86.36,133.73 84.37,133.73 U4.A12 ; v1(113.36,139.37) 113.44,139.45 CN6.28 ; v1(155.07,152.69) CN4.10
  L4_SIG w0.102: v1(111.63,163.07) 120.02,163.07 121.41,161.67 126.62,161.67 127.81,160.48 148.51,160.48 149.61,159.38 151,159.38 152.39,158 152.39,154.76 154.46,152.69 v1(155.07,152.69) 155.07,152.65 156.24,151.49 156.24,118.41 154,116.18 146.43,116.18 143.21,112.95 141.43,112.95 139.95,111.48 139.95,102.87 142.24,100.58 142.24,50.29 v1(140.52,48.57) ; v1(113.36,139.37) 112.66,138.67 112.66,137.68 112.14,137.16 107.44,137.16 107.14,136.86 97.36,136.86 94.97,134.47 92.2,134.47 91.85,134.11 90.55,134.11 89.79,133.35 86.77,133.35 v5(86.76,133.35)
  BOTTOM w0.127: v1(113.36,139.37) 112.6,139.37 109.65,142.32 109.65,154.8 107.57,156.88 v1(107.44,156.88)
PAR_D10: length 115.6
  TOP w0.102: 85.09,134.11 84.84,134.11 84.45,134.49 83.62,134.49 v5(83.61,134.49)
  TOP w0.127: 85.09,134.11 86.74,134.11 94.55,126.3 97.09,126.3 JP5.2 99.19,124.46 101.52,126.8 v1(106.78,126.8) 106.83,126.75 CN6.47 ; v5(83.61,134.49) U4.B11 ; v1(147.07,154.69) 147.07,154.69 CN4.5
  L4_SIG w0.102: v1(100.51,155.57) 100.86,155.22 107.04,155.22 109.17,157.35 123.32,157.35 124.08,156.59 125.22,156.59 125.93,157.3 145.34,157.3 147.07,155.57 v1(147.07,154.69)
  BOTTOM w0.127: v1(100.51,155.57) 100.69,155.57 105.08,151.18 105.08,133.83 106.63,132.28 106.63,126.95 v1(106.78,126.8)
PAR_D11: length 111.8
  TOP w0.127: v1(150.67,152.15) 150.88,152.15 151.26,152.53 151.26,153.97 151.98,154.69 CN4.6 ; v1(87.93,131.19) 92.58,126.54 92.58,123.32 94.87,121.03 107.7,121.03 108.33,120.4 CN6.57 111.53,120.4 v1(111.84,120.7) ; v5(82.01,133.69) U4.D12
  L4_SIG w0.102: v1(150.67,152.15) 150.67,152.12 149.73,151.18 149.73,146.69 150.37,146.05 151.13,146.05 152.27,144.91 152.27,142.39 151.49,141.6 150.19,141.6 149.66,141.07 149.66,140.16 147.4,137.9 145.8,137.9 139.73,143.97 133.48,143.97 115.77,126.26 115.77,122.68 113.94,120.85 112.01,120.85 111.86,120.7 v1(111.84,120.7) ; v5(82.01,133.69) 82.45,133.24 83.85,133.24 84.89,132.21 86.71,132.21 87.17,131.75 87.73,131.19 v1(87.93,131.19)
  BOTTOM w0.127: v1(111.84,120.7) 111.56,120.42 111.56,120.4 SB63.2
PB0: length 109.1
  TOP w0.127: U4.R5 69.71,139.69 68.2,138.18 63.88,138.18 49.91,124.21 CN5.52 v1(44.96,124.21) ; R95.2 36.5,109.35 37.01,108.84 v1(37.01,107.19)
  L4_SIG w0.102: v1(44.96,124.21) 48.84,124.21 48.97,124.33 48.97,124.74 48.84,124.87 40.97,124.87 40.84,124.74 40.84,124.48 40.97,124.35 42.29,124.35 42.39,124.25 42.39,124.07 42.27,123.94 40.89,123.94 40.79,123.84 40.79,123.64 40.89,123.54 42.27,123.54 42.39,123.41 42.39,123.26 42.27,123.13 40.89,123.13 40.79,123.03 40.79,122.83 40.89,122.73 42.27,122.73 42.39,122.6 42.39,122.45 42.27,122.32 40.89,122.32 40.79,122.22 40.79,122.01 40.89,121.91 42.27,121.91 42.39,121.79 42.39,121.63 42.27,121.51 40.89,121.51 40.79,121.4 40.79,121.2 40.89,121.1 42.27,121.1 42.39,120.97 42.39,120.82 42.27,120.69 40.94,120.69 40.84,120.59 40.84,120.39 40.94,120.29 42.27,120.29 42.39,120.16 42.39,120.01 42.27,119.88 40.94,119.88 40.84,119.78 40.84,119.58 40.94,119.47 42.27,119.47 42.39,119.35 42.39,119.2 42.27,119.07 40.94,119.07 40.84,118.97 40.84,118.76 40.94,118.66 42.27,118.66 42.39,118.53 42.39,118.38 42.27,118.26 40.94,118.26 40.84,118.15 40.84,117.95 40.94,117.85 42.27,117.85 42.39,117.72 42.39,117.57 42.27,117.44 40.94,117.44 40.84,117.34 40.84,117.14 40.94,117.04 42.48,117.04 42.6,116.92 42.6,116.75 42.48,116.63 40.94,116.63 40.84,116.53 40.84,116.32 40.94,116.22 42.45,116.22 42.57,116.1 42.57,115.94 42.45,115.82 40.94,115.82 40.84,115.72 40.84,115.51 40.94,115.41 42.43,115.41 42.55,115.29 42.55,115.12 42.43,115 40.94,115 40.84,114.9 40.84,114.7 40.94,114.6 42.48,114.6 42.6,114.48 42.6,114.31 42.48,114.19 41.12,114.19 41.02,114.09 41.02,111.2 v1(37.01,107.19)
  BOTTOM w0.127: SB59.2 v1(44.96,124.21)
PB1: length 109.1
  TOP w0.127: v1(34.8,108.71) 35.43,108.08 R100.2 ; v1(44.83,140.72) CN5.26 61.98,140.72 62.67,140.02 64.94,140.02 65.38,139.57 67.44,139.57 68.35,140.49 U4.R4
  L4_SIG w0.102: v1(34.8,108.71) 38.51,112.42 38.51,138.53 38.63,138.66 43.06,138.66 43.18,138.78 43.18,138.95 43.06,139.07 38.63,139.07 38.51,139.19 38.51,139.35 38.63,139.47 42.81,139.47 42.93,139.59 42.93,139.76 42.81,139.88 38.65,139.88 38.53,140 38.53,140.17 38.65,140.29 42.8,140.29 42.93,140.41 42.93,140.59 42.8,140.72 38.63,140.72 38.51,140.84 38.51,141.07 38.63,141.2 50.29,141.2 50.42,141.07 50.42,140.84 50.29,140.72 v1(44.83,140.72)
  BOTTOM w0.127: SB39.2 44.96,140.84 v1(44.83,140.72)
PB2: length 58.6
  TOP w0.127: v1(64.14,136.78) 65.79,136.78 R42.2 ; U3.16 27.43,143.89 27.56,143.76 27.56,141.53 27.69,141.4 28.07,141.4 28.19,141.53 28.19,143.99 28.32,144.12 28.7,144.12 28.83,143.99 28.83,141.35 28.96,141.22 29.34,141.22 29.46,141.35 29.46,144.02 29.59,144.15 29.97,144.15 30.1,144.02 30.1,140.84 30.23,140.72 39.12,140.72 39.24,140.59 39.24,138.3 39.37,138.18 CN5.29 43.05,138.18 v1(43.64,138.76)
  L4_SIG w0.102: v1(64.14,136.78) 63.12,135.76 56.82,135.76 53.82,138.76 v1(43.64,138.76)
PB3: length 30
  TOP w0.127: U4.A10 85.7,135.69 86.51,134.87 87.09,134.87 87.59,134.38 87.59,133.77 91.19,130.18 97.79,130.18 JP4.2 100.58,127.38 108.2,127.38 108.84,128.02 CN6.45
PB4: length 219.6
  TOP w0.102: 85.09,136.49 U4.A9
  TOP w0.127: U21.19 40.78,33.9 40.96,33.72 41.34,33.72 v1(41.78,34.16) ; CN6.24 v1(113.54,141.99) ; v5(87.23,135.82) 87.22,135.82 86.55,136.49 85.09,136.49 ; v1(123.06,102.23) 124.97,102.23 R112.2
  L4_SIG w0.102: v1(123.06,102.23) 123.77,101.52 123.77,99.95 117.68,93.85 115.62,93.85 111.05,89.28 111.05,78.89 108.29,76.14 107.28,76.14 105.56,74.42 105.56,73.28 89.94,57.66 88.65,57.66 87.76,56.77 87.76,55.47 76.48,44.2 75.29,44.2 73.51,42.42 56.9,42.42 55.63,41.15 51.79,41.15 49.15,38.51 49.15,33.96 48.13,32.94 42.82,32.94 41.78,33.99 v1(41.78,34.16) ; v5(87.23,135.82) 87.37,135.69 88.06,135.69 88.38,135.37 88.89,135.37 89.61,136.09 94.69,136.09 98.68,140.08 108.2,140.08 110.74,142.62 112.9,142.62 v1(113.54,141.99) 125.09,141.99 v1(125.86,142.75)
  BOTTOM w0.127: v1(123.06,102.23) 121.51,103.78 121.51,111.35 126.62,116.46 126.62,141.86 125.86,142.62 v1(125.86,142.75)
PB5: length 114.5
  TOP w0.127: CN5.4 45.73,154.69 45.02,153.97 45.02,153.35 v1(44.7,153.03) ; U4.A8 84.09,137.21 v5(84.61,137.21) ; v1(31.7,104.52) 31.7,104.39 33.27,102.82 33.27,102.36 33.53,102.11 34.92,102.11 R119.2
  L4_SIG w0.102: v5(84.61,137.21) 84.12,137.69 80.62,137.69 80.01,138.3 80.01,138.59 79.67,138.93 79.46,138.93 78.49,139.91 78.49,140.67 77.62,141.53 77.62,141.78 77.36,142.04 77.09,142.04 76.78,142.35 76.78,142.67 70.87,148.59 67.92,148.59 65.91,150.6 53.98,150.6 51.41,153.16 44.83,153.16 v1(44.7,153.03) 44.25,152.58 41.81,152.58 36.2,146.96 36.2,145.52 33.96,143.28 33.96,139.5 34.37,139.09 34.37,129.04 32,126.68 32,119.38 34.54,116.84 34.54,112.52 31.7,109.68 v1(31.7,104.52)
